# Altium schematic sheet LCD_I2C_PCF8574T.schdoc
size 127 x 101 mm; Device: Altium_Custom(500*400); Name: Altium_Custom(500*400); Width: 500; Height: 400; X Region Count: 0; Y Region Count: 0; Blade Width: 0; Region Start: 1; Border: 1; Title Block Position: 3
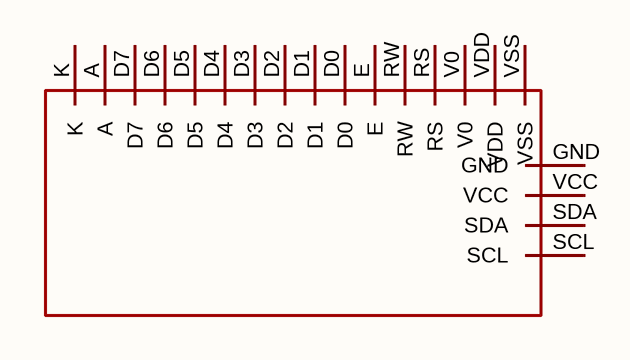
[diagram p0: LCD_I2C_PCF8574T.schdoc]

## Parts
U?  lcd_i2c_pcf8574t  [I2C MODULE]  (value not drawn)

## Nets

Not connected (* = marked no-connect by the designer): U? A D0 D1 D2 D3 D4 D5 D6 D7 E GND K RS RW SCL SDA V0 VCC VDD VSS

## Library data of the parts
U? = lcd_i2c_pcf8574t: Add into BOM: yes; UniqueId: 9ed71a516f516319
